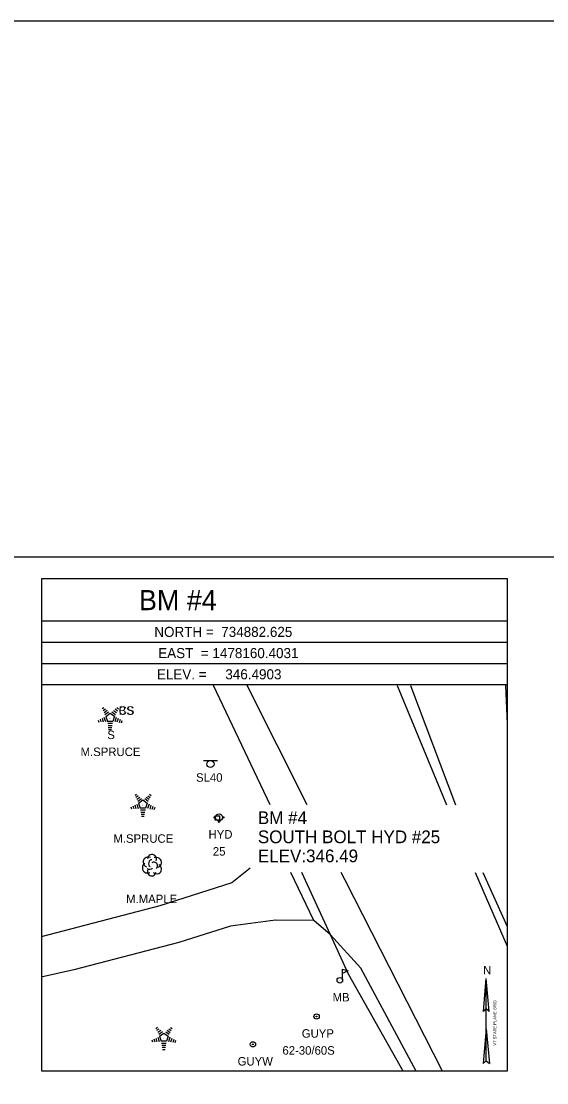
# Model space of a CAD drawing. Extents: x 1478584 to 1479224, y 735365 to 735785.
# Drawn here: x 1478854.7 to 1478978.7, y 735534.2 to 735784.5 of the extents above; entities that cross this region are included whole.
import ezdxf

# ---------------------------------------------------------------- set-up
doc = ezdxf.new("R2010")
doc.units = 0
for name, color, linetype in [('CPBM', 7, 'Continuous'), ('L_A', 7, 'Continuous'), ('L_C', 7, 'Continuous'), ('LELB', 7, 'Continuous'), ('LMB', 7, 'Continuous'), ('LTC', 7, 'Continuous'), ('LTD', 7, 'Continuous'), ('NBL1', 7, 'Continuous'), ('NBL2', 7, 'Continuous'), ('NNA_P', 7, 'Continuous'), ('PET', 7, 'Continuous'), ('PSP', 7, 'Continuous'), ('PSU', 7, 'Continuous'), ('RDG', 7, 'Continuous'), ('RDP', 7, 'Continuous'), ('S_C', 7, 'Continuous'), ('SSGN', 7, 'Continuous'), ('U_A', 7, 'Continuous'), ('U_C', 7, 'Continuous'), ('UPGW', 7, 'Continuous'), ('UWFH', 7, 'Continuous')]:
    doc.layers.add(name, color=color, linetype=linetype)

msp = doc.modelspace()

# ---------------------------------------------------------------- linework, layer by layer
at = {"layer": 'CPBM'}
for p, q in [((1478900.46, 735596.14), (1478900.46, 735597.14)), ((1478900.46, 735597.14), (1478901.46, 735597.14)), ((1478901.46, 735596.14), (1478900.46, 735596.14)), ((1478900.96, 735596.64), (1478900.96, 735596.64)), ((1478900.96, 735596.64), (1478900.96, 735596.64)), ((1478901.46, 735597.14), (1478901.46, 735596.14))]:
    msp.add_line(p, q, dxfattribs=at)
at = {"layer": 'LELB'}
msp.add_lwpolyline([(1478968.99, 735627.87), (1478969.38, 735618.81)], dxfattribs=at)
at = {"layer": 'LMB'}
for p, q in [((1478930.5, 735558.37), (1478930.5, 735560.97)), ((1478930.5, 735560.96), (1478931.79, 735560.58)), ((1478930.5, 735560.06), (1478931.78, 735560.57)), ((1478929.85, 735558.36), (1478929.85, 735558.36))]:
    msp.add_line(p, q, dxfattribs=at)
msp.add_circle((1478929.85, 735558.36), 0.656, dxfattribs=at)
at = {"layer": 'LTC'}
for p, q in [((1478873.8, 735622.45), (1478874.15, 735622.71)), ((1478874.01, 735621.98), (1478874.54, 735622.37)), ((1478874.22, 735621.52), (1478874.92, 735622.03)), ((1478874.43, 735621.05), (1478875.31, 735621.69)), ((1478874.65, 735620.6), (1478875.66, 735621.33)), ((1478874.65, 735620.6), (1478875.04, 735619.4)), ((1478875.66, 735621.33), (1478876.66, 735620.61)), ((1478876.08, 735621.64), (1478876.89, 735621.06)), ((1478876.66, 735620.61), (1478876.27, 735619.4)), ((1478876.46, 735621.99), (1478877.13, 735621.5)), ((1478876.83, 735622.34), (1478877.38, 735621.94)), ((1478877.2, 735622.69), (1478877.62, 735622.38)), ((1478872.83, 735619.73), (1478872.98, 735619.26)), ((1478873.29, 735619.94), (1478873.5, 735619.29)), ((1478873.74, 735620.16), (1478874.01, 735619.33)), ((1478874.2, 735620.38), (1478874.53, 735619.36)), ((1478876.27, 735619.4), (1478875.04, 735619.4)), ((1478876.23, 735618.9), (1478875.09, 735618.9)), ((1478876.15, 735618.4), (1478875.16, 735618.4)), ((1478877.1, 735620.34), (1478876.76, 735619.3)), ((1478877.54, 735620.09), (1478877.26, 735619.2)), ((1478877.99, 735619.84), (1478877.75, 735619.11)), ((1478878.43, 735619.58), (1478878.25, 735619.01)), ((1478876.06, 735617.9), (1478875.23, 735617.9)), ((1478875.98, 735617.4), (1478875.31, 735617.4)), ((1478881.54, 735601.99), (1478881.89, 735602.25)), ((1478881.75, 735601.53), (1478882.27, 735601.91)), ((1478881.95, 735601.06), (1478882.66, 735601.57)), ((1478882.16, 735600.6), (1478883.04, 735601.24)), ((1478882.39, 735600.14), (1478883.4, 735600.88)), ((1478883.4, 735600.88), (1478884.4, 735600.15)), ((1478883.82, 735601.19), (1478884.63, 735600.6)), ((1478884.19, 735601.54), (1478884.87, 735601.04)), ((1478884.56, 735601.89), (1478885.11, 735601.49)), ((1478884.93, 735602.23), (1478885.35, 735601.93)), ((1478880.57, 735599.27), (1478880.72, 735598.81)), ((1478881.02, 735599.49), (1478881.24, 735598.84)), ((1478881.48, 735599.71), (1478881.75, 735598.87)), ((1478881.93, 735599.92), (1478882.27, 735598.9)), ((1478882.39, 735600.14), (1478882.78, 735598.95)), ((1478884.01, 735598.95), (1478882.78, 735598.95)), ((1478883.97, 735598.45), (1478882.82, 735598.45)), ((1478884.4, 735600.15), (1478884.01, 735598.95)), ((1478884.84, 735599.88), (1478884.5, 735598.84)), ((1478885.28, 735599.63), (1478884.99, 735598.75)), ((1478885.72, 735599.38), (1478885.49, 735598.65)), ((1478886.17, 735599.13), (1478885.98, 735598.56)), ((1478883.88, 735597.95), (1478882.9, 735597.95)), ((1478883.8, 735597.45), (1478882.97, 735597.45)), ((1478883.72, 735596.95), (1478883.04, 735596.95)), ((1478886.48, 735547.02), (1478886.83, 735547.28)), ((1478886.69, 735546.56), (1478887.22, 735546.94)), ((1478886.9, 735546.09), (1478887.6, 735546.6)), ((1478887.11, 735545.63), (1478887.99, 735546.26)), ((1478887.33, 735545.17), (1478888.35, 735545.91)), ((1478888.35, 735545.91), (1478889.34, 735545.18)), ((1478888.77, 735546.22), (1478889.57, 735545.63)), ((1478889.14, 735546.57), (1478889.82, 735546.07)), ((1478889.51, 735546.92), (1478890.06, 735546.52)), ((1478889.88, 735547.26), (1478890.3, 735546.96)), ((1478885.51, 735544.3), (1478885.66, 735543.84)), ((1478885.97, 735544.52), (1478886.18, 735543.87)), ((1478886.42, 735544.74), (1478886.69, 735543.9)), ((1478886.88, 735544.95), (1478887.21, 735543.93)), ((1478887.33, 735545.17), (1478887.72, 735543.98)), ((1478888.95, 735543.98), (1478887.72, 735543.98)), ((1478888.91, 735543.48), (1478887.77, 735543.48)), ((1478888.83, 735542.98), (1478887.84, 735542.98)), ((1478889.34, 735545.18), (1478888.95, 735543.98)), ((1478889.78, 735544.91), (1478889.44, 735543.87)), ((1478890.22, 735544.66), (1478889.94, 735543.78)), ((1478890.67, 735544.41), (1478890.43, 735543.68)), ((1478891.11, 735544.16), (1478890.93, 735543.59)), ((1478888.75, 735542.48), (1478887.91, 735542.48)), ((1478888.66, 735541.98), (1478887.99, 735541.98))]:
    msp.add_line(p, q, dxfattribs=at)
at = {"layer": 'LTD'}
msp.add_line((1478885.5, 735585.55), (1478885.5, 735585.55), dxfattribs=at)
msp.add_line((1478885.5, 735585.55), (1478885.5, 735585.55), dxfattribs=at)
msp.add_arc((1478885.54, 735586.98), 1.05, 335.5272, 180.9563, dxfattribs=at)
for centre, major_axis, ratio, start_param, end_param in [((1478884.41, 735584.84), (0.58, -1.04), 0.959034, 3.141593, 6.283185), ((1478884.71, 735586.21), (1.21, -0.51), 0.895232, 1.570796, 4.712389), ((1478885.29, 735586.01), (-0.208, -0.792), 0.645439, 3.141593, 6.283185), ((1478886, 735585.38), (-0.5, 0.667), 0.989748, 3.141593, 6.283185), ((1478886.5, 735584.71), (-1.09, 0.79), 0.841452, 1.570796, 4.712389), ((1478886.54, 735586.13), (-1.14, -0.48), 0.949671, 1.570796, 4.712389), ((1478885.5, 735584.05), (0.26, 1.06), 0.942809, 1.570796, 4.712389), ((1478885.04, 735584.8), (-0.625, -0.083), 0.423636, 0, 3.141593)]:
    msp.add_ellipse(centre, major_axis=major_axis, ratio=ratio, start_param=start_param, end_param=end_param, dxfattribs=at)
at = {"layer": 'NBL1'}
msp.add_lwpolyline([(1478584.46, 735364.52), (1479224.46, 735364.52), (1479224.46, 735784.52), (1478584.46, 735784.52)], close=True, dxfattribs=at)
at = {"layer": 'NBL2'}
for p, q in [((1478584.46, 735658.18), (1479224.46, 735658.18)), ((1478969.46, 735643.02), (1478859.46, 735643.02)), ((1478969.46, 735638.02), (1478859.46, 735638.02)), ((1478969.46, 735633.02), (1478859.46, 735633.02)), ((1478969.46, 735628.02), (1478859.46, 735628.02))]:
    msp.add_line(p, q, dxfattribs=at)
msp.add_lwpolyline([(1478859.46, 735537.02), (1478969.46, 735537.02), (1478969.46, 735653.02), (1478859.46, 735653.02)], close=True, dxfattribs=at)
at = {"layer": 'NNA_P'}
for p, q in [((1478963.73, 735550.98), (1478964.43, 735558.77)), ((1478964.43, 735539.39), (1478964.43, 735558.77)), ((1478965.12, 735550.98), (1478964.43, 735558.77)), ((1478963.73, 735550.98), (1478964.43, 735551.74)), ((1478965.12, 735550.98), (1478964.43, 735551.74)), ((1478964.43, 735546.92), (1478963.71, 735538.75)), ((1478964.43, 735546.92), (1478965.15, 735538.75)), ((1478964.43, 735539.39), (1478963.71, 735538.75)), ((1478964.43, 735539.39), (1478965.15, 735538.75))]:
    msp.add_line(p, q, dxfattribs=at)
at = {"layer": 'PET'}
for points in [[(1478922.13, 735599.77), (1478907.96, 735627.87)], [(1478943.41, 735627.87), (1478955.04, 735599.77)], [(1478954.06, 735536.92), (1478931.1, 735581.97), (1478930.19, 735583.77)], [(1478961.8, 735583.77), (1478969.38, 735566.44)]]:
    msp.add_lwpolyline(points, dxfattribs=at)
at = {"layer": 'PSP'}
for points in [[(1478913.43, 735599.77), (1478900.02, 735627.87)], [(1478946.56, 735627.87), (1478957.18, 735599.77)], [(1478947.9, 735536.92), (1478934.8, 735561.19), (1478927.66, 735569.1), (1478920.88, 735583.77)], [(1478963.64, 735583.77), (1478969.38, 735571.06)]]:
    msp.add_lwpolyline(points, dxfattribs=at)
at = {"layer": 'PSU'}
msp.add_lwpolyline([(1478944.84, 735536.92), (1478931.89, 735559.77), (1478927.66, 735569.1)], dxfattribs=at)
at = {"layer": 'RDG'}
for points in [[(1478908.68, 735584.79), (1478904.34, 735581.37), (1478887.4, 735575.88), (1478859.36, 735568.64)], [(1478923.69, 735572.48), (1478914.65, 735572.54), (1478904.07, 735571.11), (1478891.86, 735567.24), (1478867.1, 735560.86), (1478859.36, 735559.09)]]:
    msp.add_lwpolyline(points, dxfattribs=at)
at = {"layer": 'RDP'}
msp.add_lwpolyline([(1478927.66, 735569.1), (1478923.69, 735572.48), (1478918.31, 735583.77)], dxfattribs=at)
at = {"layer": 'SSGN'}
for p, q in [((1478897.69, 735610.18), (1478901.02, 735610.18)), ((1478899.34, 735609.35), (1478899.34, 735609.35))]:
    msp.add_line(p, q, dxfattribs=at)
msp.add_circle((1478899.34, 735609.35), 0.833, dxfattribs=at)
at = {"layer": 'UPGW'}
for centre, radius in [((1478924.37, 735549.82), 0.625), ((1478924.37, 735549.82), 0.0833), ((1478909.35, 735543.26), 0.625), ((1478909.35, 735543.26), 0.0833)]:
    msp.add_circle(centre, radius, dxfattribs=at)
at = {"layer": 'UWFH'}
msp.add_line((1478901.36, 735596.77), (1478901.36, 735596.77), dxfattribs=at)
for centre, radius in [((1478900.36, 735596.77), 0.167), ((1478901.36, 735596.77), 0.833), ((1478901.36, 735595.77), 0.167), ((1478902.36, 735596.77), 0.167)]:
    msp.add_circle(centre, radius, dxfattribs=at)

# ---------------------------------------------------------------- texts
at = {"layer": 'L_A'}
for s, p in [('CS', (1478877.67, 735620.97)), ('BS', (1478877.67, 735620.97)), ('S', (1478874.99, 735615.24)), ('MB', (1478928.15, 735553.36))]:
    msp.add_text(s, height=2, dxfattribs=at).set_placement(p)
at = {"layer": 'L_C'}
for s, p in [('M.SPRUCE', (1478868.69, 735611.24)), ('M.SPRUCE', (1478876.43, 735590.79)), ('M.MAPLE', (1478879.43, 735576.55))]:
    msp.add_text(s, height=2, dxfattribs=at).set_placement(p)
at = {"layer": 'LTC'}
for p in [(1478875.55, 735620.34), (1478883.28, 735599.89), (1478888.23, 735544.92)]:
    msp.add_text('.', height=1.04, rotation=270, dxfattribs=at).set_placement(p)
at = {"layer": 'NBL2'}
for s, height, p in [('       BM #4       ', 4.75, (1478870.11, 735645.64)), ('NORTH =  734882.625 ', 2.375, (1478886.08, 735639.33)), ('EAST  = 1478160.4031', 2.375, (1478887, 735634.33)), ('ELEV. =     346.4903', 2.375, (1478886.69, 735629.33)), ('BM #4', 3, (1478910.52, 735595.19)), ('SOUTH BOLT HYD #25', 3, (1478910.52, 735590.69)), ('ELEV:346.49', 3, (1478910.52, 735586.19))]:
    msp.add_text(s, height=height, dxfattribs=at).set_placement(p)
at = {"layer": 'NNA_P'}
msp.add_text('N', height=1.97, dxfattribs=at).set_placement((1478963.66, 735559.78))
msp.add_text('VT STATE PLANE GRID', height=0.7, rotation=90.0204, dxfattribs=at).set_placement((1478966.78, 735542.96))
at = {"layer": 'S_C'}
msp.add_text('SL40', height=2, dxfattribs=at).set_placement((1478895.93, 735605.18))
at = {"layer": 'U_A'}
for s, p in [('HYD', (1478898.88, 735591.77)), ('GUYP', (1478920.88, 735544.82)), ('GUYW', (1478905.75, 735538.26))]:
    msp.add_text(s, height=2, dxfattribs=at).set_placement(p)
at = {"layer": 'U_C'}
for s, p in [('25', (1478899.9, 735587.77)), ('62-30/60S', (1478916.32, 735540.82))]:
    msp.add_text(s, height=2, dxfattribs=at).set_placement(p)

doc.saveas('drawing.dxf')
